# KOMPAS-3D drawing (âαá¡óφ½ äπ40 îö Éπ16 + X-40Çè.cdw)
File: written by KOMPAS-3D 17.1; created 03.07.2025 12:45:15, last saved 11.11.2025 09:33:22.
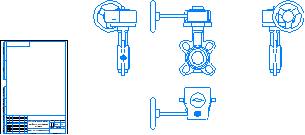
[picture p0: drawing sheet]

Sheet 1: A4, portrait

Title block, sheet 1: name: ГЧ Гранвэл Ду40 МФ Ру16 / + X-40АК (Габаритный / чертёж); material: Сталь 20  ГОСТ 1050-2013; mass: 2,04; sheets: 1; sheet format: A4; stored path: \\adlc.lan\data\АДЛ_ПКД\3D-модели\ADL production\Дисковые поворотные затворы ГРАНВЭЛ\межфланцевый с китайским редуктором Ру16\KOMPAS 2D\Гранвэл Ду40 МФ Ру16 + X-40АК.cdw

Views: Вид 1, Спереди, Проекционный вид 2, Проекционный вид 3, Проекционный вид 4
Referenced files in \\adlc.lan\data\АДЛ_ПКД\3D-модели\ADL production\Дисковые поворотные затворы ГРАНВЭЛ\межфланцевый с китайским редуктором Ру16\KOMPAS 3D\: Гранвэл Ду40 МФ Ру16 + X-40АК.m3d
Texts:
  Andrey
  АДЛ
Dimensions and other numbers on the sheet: 1:1; 1; 2,04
